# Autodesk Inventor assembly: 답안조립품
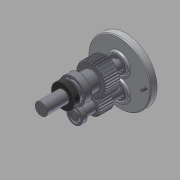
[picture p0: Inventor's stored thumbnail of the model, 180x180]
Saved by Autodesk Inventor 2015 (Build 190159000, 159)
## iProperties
Created: 2016-02
Part Number: 답안조립품
Document SubType Name: Assembly
Designer: Administrator
Author: Administrator
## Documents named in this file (10)
- C:\Users\Administrator\Desktop\460209V1012\답안조립품.iam
- C:\Users\Administrator\Desktop\460209V1012\본체.ipt
- C:\Users\Administrator\Desktop\460209V1012\커버.ipt
- C:\Users\Administrator\Desktop\460209V1012\오일실 17 32 8.ipt
- C:\Users\Administrator\Desktop\460209V1012\오일실 8 22 7.ipt
- C:\Users\Administrator\Desktop\460209V1012\볼트 M4 x 10.ipt
- C:\Users\Administrator\Desktop\460209V1012\베어링 6003.ipt
- C:\Users\Administrator\Desktop\460209V1012\베어링 608.ipt
- C:\Users\Administrator\Desktop\460209V1012\서브축.ipt
- C:\Users\Administrator\Desktop\460209V1012\메인축.ipt
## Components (2 placed, 1 different names)
1. ISO 4762 M4 x 10:1 — Insert:1
2. ISO 4762 M4 x 10:2 — Insert:2
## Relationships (2: Insert 2)
- Insert:1: ISO 4762 M4 x 10:1
- Insert:2: ISO 4762 M4 x 10:2
